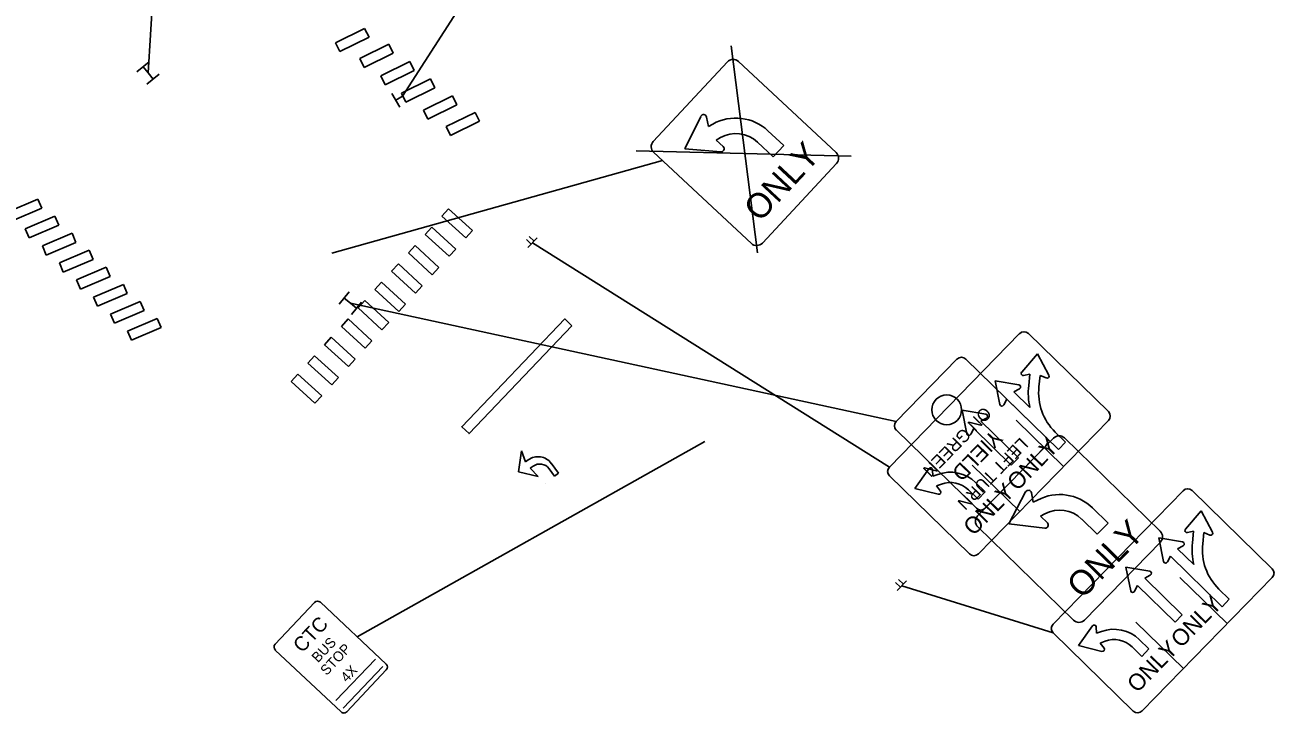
# Model space of a CAD drawing. Extents: x 1479394 to 1483660, y 379804 to 384342.
# Drawn here: x 1479604.6 to 1479855.8, y 379803.8 to 379942.2 of the extents above; entities that cross this region are included whole.
import ezdxf

# ---------------------------------------------------------------- set-up
doc = ezdxf.new("R2010")
doc.units = 0
for name, color, linetype in [('PM_P_Cells', 7, 'Continuous'), ('PM_P_Stop_Line', 7, 'Continuous'), ('RD_P_Text', 7, 'Continuous'), ('SC_Scratch15', 7, 'Continuous'), ('SC_Scratch3', 7, 'Continuous'), ('SH_Text', 7, 'Continuous')]:
    doc.layers.add(name, color=color, linetype=linetype)

msp = doc.modelspace()

# ---------------------------------------------------------------- linework, layer by layer
at = {"layer": 'PM_P_Cells'}
for p, q in [((1479704.48, 379856.53), (1479703.86, 379852.3)), ((1479704.48, 379856.53), (1479704.48, 379856.53)), ((1479705.27, 379854.33), (1479704.48, 379856.53)), ((1479705.81, 379854.72), (1479705.27, 379854.33)), ((1479711.9, 379852.04), (1479710.43, 379854.04)), ((1479703.86, 379852.3), (1479707.8, 379851.42)), ((1479706.21, 379853.04), (1479706.78, 379853.45)), ((1479707.8, 379851.42), (1479706.21, 379853.04)), ((1479709.99, 379852.95), (1479711.09, 379851.45)), ((1479711.09, 379851.45), (1479711.9, 379852.04)), ((1479709.21, 379850.07), (1479709.21, 379850.07))]:
    msp.add_line(p, q, dxfattribs=at)
for centre, radius, end in [((1479707.79, 379852.1), 3.28, 127.0854), ((1479708.14, 379851.6), 2.3, 126.1769)]:
    msp.add_arc(centre, radius, 36.1769, end, dxfattribs=at)
at = {"layer": 'PM_P_Stop_Line'}
msp.add_lwpolyline([(1479714.59, 379881.7), (1479713.16, 379883.11), (1479692.45, 379861.39), (1479693.91, 379860.02)], close=True, dxfattribs=at)
at = {"layer": 'RD_P_Text'}
for p, q in [((1479627.09, 379932.81), (1479629.58, 379934.83)), ((1479628.33, 379933.82), (1479629.35, 379932.58)), ((1479631.6, 379932.35), (1479629.12, 379930.33)), ((1479630.36, 379931.34), (1479629.35, 379932.58)), ((1479679.96, 379925.7), (1479678.35, 379928.47)), ((1479679.16, 379927.09), (1479680.54, 379927.89)), ((1479667.78, 379886.03), (1479669.81, 379888.51)), ((1479668.8, 379887.27), (1479670.03, 379886.25)), ((1479671.27, 379885.24), (1479670.03, 379886.25)), ((1479672.29, 379886.48), (1479670.26, 379884))]:
    msp.add_line(p, q, dxfattribs=at)
at = {"layer": 'SC_Scratch15'}
for p, q in [((1479635.28, 380024.91), (1479629.35, 379932.58)), ((1479680.54, 379927.89), (1479743.52, 380026.03)), ((1479751.92, 379896.37), (1479746.62, 379938.05)), ((1479740.51, 379923.85), (1479737.27, 379917.34)), ((1479742.07, 379921.81), (1479741.68, 379923.7)), ((1479742.94, 379922.29), (1479742.07, 379921.81)), ((1479743.6, 379919.08), (1479744.46, 379919.57)), ((1479757.22, 379917.96), (1479754.02, 379920.95)), ((1479727.52, 379916.92), (1479770.77, 379915.81)), ((1479737.27, 379917.34), (1479744.51, 379916.68)), ((1479745, 379917.75), (1479743.6, 379919.08)), ((1479751.89, 379918.66), (1479755.09, 379915.68)), ((1479755.09, 379915.68), (1479757.22, 379917.96)), ((1479666.29, 379896.3), (1479732.81, 379914.95)), ((1479707.63, 379899.41), (1479705.75, 379897.45)), ((1479706.97, 379898.73), (1479705.99, 379899.67)), ((1479706.41, 379898.14), (1479705.43, 379899.08)), ((1479778.44, 379853.28), (1479706.69, 379898.43)), ((1479706.69, 379898.43), (1479706.69, 379898.43)), ((1479706.69, 379898.43), (1479706.69, 379898.43)), ((1479670.03, 379886.25), (1479779.82, 379862.47)), ((1479808.21, 379876.05), (1479805.05, 379872.39)), ((1479810.49, 379871.79), (1479808.21, 379876.05)), ((1479805.44, 379871.71), (1479806.71, 379871.95)), ((1479806.71, 379871.95), (1479806.46, 379869.67)), ((1479808.53, 379869.44), (1479808.78, 379871.73)), ((1479808.78, 379871.73), (1479809.96, 379871.21)), ((1479799.73, 379870.64), (1479800.67, 379865.89)), ((1479804.49, 379869.82), (1479799.73, 379870.64)), ((1479803.49, 379868.43), (1479804.62, 379869.04)), ((1479801.45, 379865.79), (1479802.03, 379866.94)), ((1479802.03, 379866.94), (1479812.43, 379856.8)), ((1479806.71, 379865.28), (1479803.49, 379868.43)), ((1479793.1, 379864.73), (1479794.04, 379859.99)), ((1479797.86, 379863.91), (1479793.1, 379864.73)), ((1479796.86, 379862.52), (1479797.99, 379863.14)), ((1479804.42, 379855.15), (1479796.86, 379862.52)), ((1479803.92, 379862.7), (1479813.46, 379853.39)), ((1479794.82, 379859.88), (1479795.4, 379861.03)), ((1479795.4, 379861.03), (1479802.96, 379853.66)), ((1479813.88, 379858.29), (1479811.79, 379860.33)), ((1479812.43, 379856.8), (1479813.88, 379858.29)), ((1479802.96, 379853.66), (1479804.42, 379855.15)), ((1479783.57, 379849), (1479786.36, 379852.95)), ((1479787.12, 379852.73), (1479787.19, 379851.44)), ((1479787.19, 379851.44), (1479788.17, 379851.8)), ((1479795.12, 379853.67), (1479804.66, 379844.36)), ((1479788.26, 379847.81), (1479783.57, 379849)), ((1479788.9, 379849.85), (1479787.91, 379849.48)), ((1479787.91, 379849.48), (1479788.69, 379848.46)), ((1479795.79, 379850.18), (1479797.73, 379848.29)), ((1479796.27, 379846.8), (1479794.33, 379848.69)), ((1479797.73, 379848.29), (1479796.27, 379846.8)), ((1479805.85, 379848.28), (1479802.47, 379841.84)), ((1479807.37, 379846.2), (1479807.02, 379848.1)), ((1479808.25, 379846.66), (1479807.37, 379846.2)), ((1479808.84, 379843.44), (1479809.71, 379843.9)), ((1479822.43, 379842.02), (1479819.3, 379845.07)), ((1479841.13, 379844.45), (1479837.97, 379840.79)), ((1479843.42, 379840.19), (1479841.13, 379844.45)), ((1479802.47, 379841.84), (1479809.7, 379841.01)), ((1479810.21, 379842.08), (1479808.84, 379843.44)), ((1479817.12, 379842.83), (1479820.25, 379839.78)), ((1479820.25, 379839.78), (1479822.43, 379842.02)), ((1479832.66, 379839.04), (1479833.6, 379834.3)), ((1479837.42, 379838.22), (1479832.66, 379839.04)), ((1479838.37, 379840.11), (1479839.63, 379840.36)), ((1479839.63, 379840.36), (1479839.38, 379838.07)), ((1479841.45, 379837.85), (1479841.71, 379840.13)), ((1479841.71, 379840.13), (1479842.89, 379839.61)), ((1479836.41, 379836.83), (1479837.55, 379837.44)), ((1479839.64, 379833.68), (1479836.41, 379836.83)), ((1479834.38, 379834.19), (1479834.96, 379835.34)), ((1479834.96, 379835.34), (1479845.35, 379825.2)), ((1479826.03, 379833.14), (1479826.97, 379828.39)), ((1479830.79, 379832.32), (1479826.03, 379833.14)), ((1479829.79, 379830.93), (1479830.92, 379831.54)), ((1479780.68, 379829.11), (1479779.7, 379830.05)), ((1479781.91, 379830.39), (1479780.02, 379828.43)), ((1479781.25, 379829.7), (1479780.27, 379830.64)), ((1479811.39, 379819.92), (1479780.97, 379829.41)), ((1479780.97, 379829.41), (1479780.97, 379829.41)), ((1479780.97, 379829.41), (1479780.97, 379829.41)), ((1479827.75, 379828.29), (1479828.33, 379829.44)), ((1479828.33, 379829.44), (1479835.89, 379822.06)), ((1479837.34, 379823.56), (1479829.79, 379830.93)), ((1479836.84, 379831.1), (1479846.39, 379821.79)), ((1479846.81, 379826.69), (1479844.72, 379828.73)), ((1479845.35, 379825.2), (1479846.81, 379826.69)), ((1479816.5, 379817.4), (1479819.29, 379821.35)), ((1479828.04, 379822.08), (1479837.59, 379812.77)), ((1479835.89, 379822.06), (1479837.34, 379823.56)), ((1479820.05, 379821.13), (1479820.11, 379819.84)), ((1479820.11, 379819.84), (1479821.1, 379820.21)), ((1479821.19, 379816.21), (1479816.5, 379817.4)), ((1479821.82, 379818.25), (1479820.83, 379817.89)), ((1479820.83, 379817.89), (1479821.62, 379816.87)), ((1479829.2, 379815.2), (1479827.26, 379817.09)), ((1479828.71, 379818.59), (1479830.65, 379816.69)), ((1479830.65, 379816.69), (1479829.2, 379815.2))]:
    msp.add_line(p, q, dxfattribs=at)
for points in [[(1479745.87, 379934.81), (1479730.95, 379918.82)], [(1479767.74, 379916.56), (1479748.08, 379934.89)], [(1479731.03, 379916.61), (1479750.69, 379898.28)], [(1479752.89, 379898.36), (1479767.81, 379914.35)], [(1479804.62, 379880.13), (1479778.44, 379853.28)], [(1479822.5, 379864.44), (1479806.39, 379880.15)], [(1479779.82, 379862.47), (1479792.03, 379875)], [(1479793.8, 379875.02), (1479809.91, 379859.32)], [(1479796.34, 379835.83), (1479822.52, 379862.67)], [(1479795.95, 379845), (1479779.84, 379860.7)], [(1479811.46, 379859.12), (1479796.19, 379843.45)], [(1479832.91, 379840.38), (1479813.67, 379859.14)], [(1479809.93, 379857.55), (1479797.72, 379845.02)], [(1479778.46, 379851.51), (1479794.57, 379835.8)], [(1479837.55, 379848.53), (1479811.37, 379821.68)], [(1479855.42, 379832.84), (1479839.31, 379848.55)], [(1479796.22, 379841.24), (1479815.46, 379822.48)], [(1479817.67, 379822.51), (1479832.94, 379838.17)], [(1479829.26, 379804.23), (1479855.45, 379831.07)], [(1479811.39, 379819.92), (1479827.5, 379804.21)]]:
    msp.add_lwpolyline(points, dxfattribs=at)
msp.add_circle((1479789.97, 379864.8), 3, dxfattribs=at)
for centre, radius, start, end in [((1479747.02, 379933.75), 1.56, 47, 137), ((1479741.07, 379923.58), 0.625, 11.7936, 153.5653), ((1479747.56, 379914.02), 9.48, 47, 119.1425), ((1479747.56, 379914.02), 6.35, 47, 119.1387), ((1479732.1, 379917.75), 1.56, 137, 227), ((1479744.57, 379917.3), 0.625, 264.7543, 46.526), ((1479766.67, 379915.42), 1.56, 317, 47), ((1479751.75, 379899.42), 1.56, 227, 317), ((1479805.52, 379879.25), 1.25, 45.7179, 135.7179), ((1479792.93, 379874.13), 1.25, 45.7261, 135.7261), ((1479805.36, 379872.12), 0.417, 139.1873, 281.0654), ((1479810.13, 379871.59), 0.417, 246.3418, 28.2199), ((1479804.42, 379869.41), 0.417, 298.3561, 80.2342), ((1479819.5, 379868.23), 13.12, 173.7036, 192.9924), ((1479819.5, 379868.23), 11.04, 173.7036, 225.7179), ((1479801.08, 379865.98), 0.417, 191.2016, 333.0797), ((1479821.62, 379863.54), 1.25, 315.7179, 45.7179), ((1479780.71, 379861.6), 1.25, 135.7261, 225.7261), ((1479797.79, 379863.5), 0.417, 298.3561, 80.2342), ((1479794.45, 379860.07), 0.417, 191.2016, 333.0797), ((1479809.04, 379858.42), 1.25, 315.7261, 45.7261), ((1479812.58, 379858.02), 1.56, 45.7261, 135.7261), ((1479779.33, 379852.41), 1.25, 135.7179, 225.7179), ((1479786.7, 379852.71), 0.417, 2.8734, 144.7515), ((1479790.7, 379844.96), 7.29, 45.7179, 110.2352), ((1479790.7, 379844.96), 5.21, 45.7179, 110.2352), ((1479838.44, 379847.66), 1.25, 45.7179, 135.7179), ((1479788.36, 379848.21), 0.417, 255.7189, 37.597), ((1479806.41, 379847.99), 0.625, 10.5197, 152.2914), ((1479812.68, 379838.28), 9.48, 45.7261, 117.8686), ((1479796.82, 379845.89), 1.25, 225.7261, 315.7261), ((1479812.68, 379838.28), 6.35, 45.7261, 117.8648), ((1479797.31, 379842.36), 1.56, 135.7261, 225.7261), ((1479809.77, 379841.63), 0.625, 263.4804, 45.2521), ((1479831.82, 379839.26), 1.56, 315.7261, 45.7261), ((1479838.29, 379840.52), 0.417, 139.1873, 281.0654), ((1479843.05, 379839.99), 0.417, 246.3418, 28.2199), ((1479837.35, 379837.81), 0.417, 298.3561, 80.2342), ((1479852.43, 379836.64), 13.12, 173.7036, 192.9924), ((1479852.43, 379836.64), 11.04, 173.7036, 225.7179), ((1479795.44, 379836.7), 1.25, 225.7179, 315.7179), ((1479834, 379834.38), 0.417, 191.2016, 333.0797), ((1479830.72, 379831.91), 0.417, 298.3561, 80.2342), ((1479854.55, 379831.95), 1.25, 315.7179, 45.7179), ((1479827.38, 379828.48), 0.417, 191.2016, 333.0797), ((1479812.26, 379820.81), 1.25, 135.7179, 225.7179), ((1479816.55, 379823.6), 1.56, 225.7261, 315.7261), ((1479819.63, 379821.11), 0.417, 2.8734, 144.7515), ((1479823.62, 379813.37), 7.29, 45.7179, 110.2352), ((1479821.29, 379816.61), 0.417, 255.7189, 37.597), ((1479823.62, 379813.37), 5.21, 45.7179, 110.2352), ((1479828.37, 379805.1), 1.25, 225.7179, 315.7179)]:
    msp.add_arc(centre, radius, start, end, dxfattribs=at)
at = {"layer": 'SC_Scratch3'}
for p, q in [((1479672.9, 379941.54), (1479667.06, 379938.67)), ((1479667.94, 379936.88), (1479673.78, 379939.75)), ((1479673.78, 379939.75), (1479672.9, 379941.54)), ((1479667.06, 379938.67), (1479667.94, 379936.88)), ((1479677.76, 379938.37), (1479671.92, 379935.5)), ((1479678.64, 379936.57), (1479677.76, 379938.37)), ((1479671.92, 379935.5), (1479672.81, 379933.71)), ((1479672.81, 379933.71), (1479678.64, 379936.57)), ((1479682.01, 379934.88), (1479676.17, 379932.01)), ((1479682.89, 379933.09), (1479682.01, 379934.88)), ((1479676.17, 379932.01), (1479677.05, 379930.22)), ((1479677.05, 379930.22), (1479682.89, 379933.09)), ((1479686.16, 379931.39), (1479680.32, 379928.52)), ((1479681.21, 379926.73), (1479687.04, 379929.6)), ((1479687.04, 379929.6), (1479686.16, 379931.39)), ((1479680.32, 379928.52), (1479681.21, 379926.73)), ((1479690.58, 379927.97), (1479684.74, 379925.1)), ((1479691.46, 379926.17), (1479690.58, 379927.97)), ((1479684.74, 379925.1), (1479685.62, 379923.31)), ((1479685.62, 379923.31), (1479691.46, 379926.17)), ((1479695.12, 379924.64), (1479689.28, 379921.78)), ((1479696, 379922.85), (1479695.12, 379924.64)), ((1479689.28, 379921.78), (1479690.16, 379919.98)), ((1479690.16, 379919.98), (1479696, 379922.85)), ((1479607.19, 379907.22), (1479601.21, 379904.67)), ((1479607.97, 379905.38), (1479607.19, 379907.22)), ((1479601.99, 379902.83), (1479607.97, 379905.38)), ((1479689.79, 379905.24), (1479688.45, 379903.76)), ((1479694.59, 379900.86), (1479689.79, 379905.24)), ((1479610.62, 379903.79), (1479604.64, 379901.24)), ((1479605.42, 379899.4), (1479611.4, 379901.95)), ((1479611.4, 379901.95), (1479610.62, 379903.79)), ((1479688.45, 379903.76), (1479693.25, 379899.38)), ((1479604.64, 379901.24), (1479605.42, 379899.4)), ((1479614.07, 379900.34), (1479608.09, 379897.79)), ((1479614.85, 379898.5), (1479614.07, 379900.34)), ((1479686.42, 379901.55), (1479685.07, 379900.07)), ((1479685.07, 379900.07), (1479689.88, 379895.69)), ((1479691.22, 379897.16), (1479686.42, 379901.55)), ((1479693.25, 379899.38), (1479694.59, 379900.86)), ((1479608.09, 379897.79), (1479608.87, 379895.95)), ((1479608.87, 379895.95), (1479614.85, 379898.5)), ((1479617.49, 379896.91), (1479611.52, 379894.36)), ((1479618.28, 379895.07), (1479617.49, 379896.91)), ((1479683.05, 379897.85), (1479681.7, 379896.38)), ((1479687.85, 379893.47), (1479683.05, 379897.85)), ((1479689.88, 379895.69), (1479691.22, 379897.16)), ((1479611.52, 379894.36), (1479612.3, 379892.52)), ((1479612.3, 379892.52), (1479618.28, 379895.07)), ((1479679.68, 379894.16), (1479678.33, 379892.68)), ((1479684.48, 379889.78), (1479679.68, 379894.16)), ((1479681.7, 379896.38), (1479686.5, 379891.99)), ((1479620.92, 379893.48), (1479614.94, 379890.93)), ((1479615.73, 379889.09), (1479621.71, 379891.64)), ((1479621.71, 379891.64), (1479620.92, 379893.48)), ((1479678.33, 379892.68), (1479683.13, 379888.3)), ((1479686.5, 379891.99), (1479687.85, 379893.47)), ((1479614.94, 379890.93), (1479615.73, 379889.09)), ((1479624.38, 379890.02), (1479618.4, 379887.47)), ((1479625.16, 379888.18), (1479624.38, 379890.02)), ((1479676.31, 379890.47), (1479674.96, 379888.99)), ((1479681.11, 379886.09), (1479676.31, 379890.47)), ((1479683.13, 379888.3), (1479684.48, 379889.78)), ((1479618.4, 379887.47), (1479619.18, 379885.63)), ((1479619.18, 379885.63), (1479625.16, 379888.18)), ((1479627.77, 379886.63), (1479621.79, 379884.08)), ((1479628.56, 379884.79), (1479627.77, 379886.63)), ((1479672.94, 379886.77), (1479671.59, 379885.3)), ((1479677.74, 379882.39), (1479672.94, 379886.77)), ((1479674.96, 379888.99), (1479679.76, 379884.61)), ((1479621.79, 379884.08), (1479622.58, 379882.24)), ((1479622.58, 379882.24), (1479628.56, 379884.79)), ((1479671.59, 379885.3), (1479676.39, 379880.91)), ((1479679.76, 379884.61), (1479681.11, 379886.09)), ((1479631.2, 379883.2), (1479625.22, 379880.65)), ((1479631.98, 379881.36), (1479631.2, 379883.2)), ((1479669.57, 379883.08), (1479668.22, 379881.6)), ((1479668.22, 379881.6), (1479673.02, 379877.22)), ((1479674.37, 379878.7), (1479669.57, 379883.08)), ((1479676.39, 379880.91), (1479677.74, 379882.39)), ((1479625.22, 379880.65), (1479626.01, 379878.81)), ((1479626.01, 379878.81), (1479631.98, 379881.36)), ((1479666.2, 379879.39), (1479664.85, 379877.91)), ((1479671, 379875.01), (1479666.2, 379879.39)), ((1479664.85, 379877.91), (1479669.65, 379873.53)), ((1479673.02, 379877.22), (1479674.37, 379878.7)), ((1479662.83, 379875.7), (1479661.48, 379874.22)), ((1479661.48, 379874.22), (1479666.28, 379869.84)), ((1479667.63, 379871.31), (1479662.83, 379875.7)), ((1479669.65, 379873.53), (1479671, 379875.01)), ((1479659.46, 379872), (1479658.11, 379870.53)), ((1479664.26, 379867.62), (1479659.46, 379872)), ((1479658.11, 379870.53), (1479662.91, 379866.14)), ((1479666.28, 379869.84), (1479667.63, 379871.31)), ((1479662.91, 379866.14), (1479664.26, 379867.62))]:
    msp.add_line(p, q, dxfattribs=at)
at = {"layer": 'SH_Text'}
for p, q in [((1479741.31, 379858.42), (1479671.37, 379819.16)), ((1479667.08, 379806.34), (1479675.11, 379814.66)), ((1479668.56, 379804.81), (1479676.59, 379813.14))]:
    msp.add_line(p, q, dxfattribs=at)
for points in [[(1479654.9, 379817.65), (1479662.83, 379826.07)], [(1479664, 379826.1), (1479677.22, 379813.65)], [(1479668.17, 379804.03), (1479654.94, 379816.48)], [(1479677.26, 379812.48), (1479669.33, 379804.06)]]:
    msp.add_lwpolyline(points, dxfattribs=at)
for centre, start, end in [((1479663.43, 379825.5), 46.7243, 136.7243), ((1479655.51, 379817.08), 136.7243, 226.7243), ((1479676.66, 379813.05), 316.7243, 46.7243), ((1479668.73, 379804.63), 226.7243, 316.7243)]:
    msp.add_arc(centre, 0.826, start, end, dxfattribs=at)

# ---------------------------------------------------------------- texts
at = {"layer": 'SC_Scratch15'}
for s, height, rotation, p in [('ONLY', 5, 47, (1479752.38, 379902.39)), ('ON GREEN', 2.503, 225.7261, (1479797.44, 379865.61)), ('YIELD', 3.128, 225.7261, (1479799.22, 379861.02)), ('LEFT TURN', 2.503, 225.7261, (1479804.78, 379859.39)), ('ONLY', 3.333, 45.7179, (1479804.17, 379848.33)), ('ONLY', 3.333, 45.7179, (1479795.37, 379839.31)), ('ONLY', 5, 45.7261, (1479817.24, 379826.55)), ('ONLY', 3.333, 45.7179, (1479837.09, 379816.73)), ('ONLY', 3.333, 45.7179, (1479828.29, 379807.71))]:
    msp.add_text(s, height=height, rotation=rotation, dxfattribs=at).set_placement(p)
at = {"layer": 'SH_Text'}
for s, height, p in [('CTC', 2.89, (1479660.33, 379815.76)), ('BUS', 2.023, (1479663.52, 379813.82)), ('STOP', 2.023, (1479665.26, 379811.24)), ('4X', 2.023, (1479669.34, 379809.85))]:
    msp.add_text(s, height=height, rotation=46.7243, dxfattribs=at).set_placement(p)

doc.saveas('drawing.dxf')
